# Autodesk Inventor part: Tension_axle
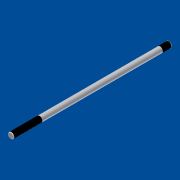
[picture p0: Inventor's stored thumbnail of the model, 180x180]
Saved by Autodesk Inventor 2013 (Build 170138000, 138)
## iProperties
Shininess: 69.0
Length Units: 11269
Angle Units: 11279
Time Units: 11290
Mass Units: 11283
Length Display Precision: 3
Angle Display Precision: 2
Created: 2001-04
Part Number: Tension_axle
Material: Standard
Document SubType Name: Modellieren
Designer: dl
Density: 1 g/cm^3
Density: 0.0
Volumn: 0.0
Area: 0.0
PropertySet Name: Model Information
Control State: 0
Master: False
Checked Out: False
Author: dl
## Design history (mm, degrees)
body "Solid1"
sketch "Sketch1"
  geometry: C1 r 2.5 at (-5.774, 4.683)
  constraints: 1 centre point
  dimensions: "d0" = 5 diameter of C1
extrude "Extrusion1" new body sketch "Sketch1" distance "d1" = 138; taper "d2" = 0 deg
thread "Thread1" dims "d5" = 25, "d6" = 0
thread "Thread2" dims "d7" = 8, "d8" = 0
chamfer "Chamfer1" distance "d3" = 0.4; stored, may be unused: second distance "d4" = 0.4, angle "d9" = 45 deg
